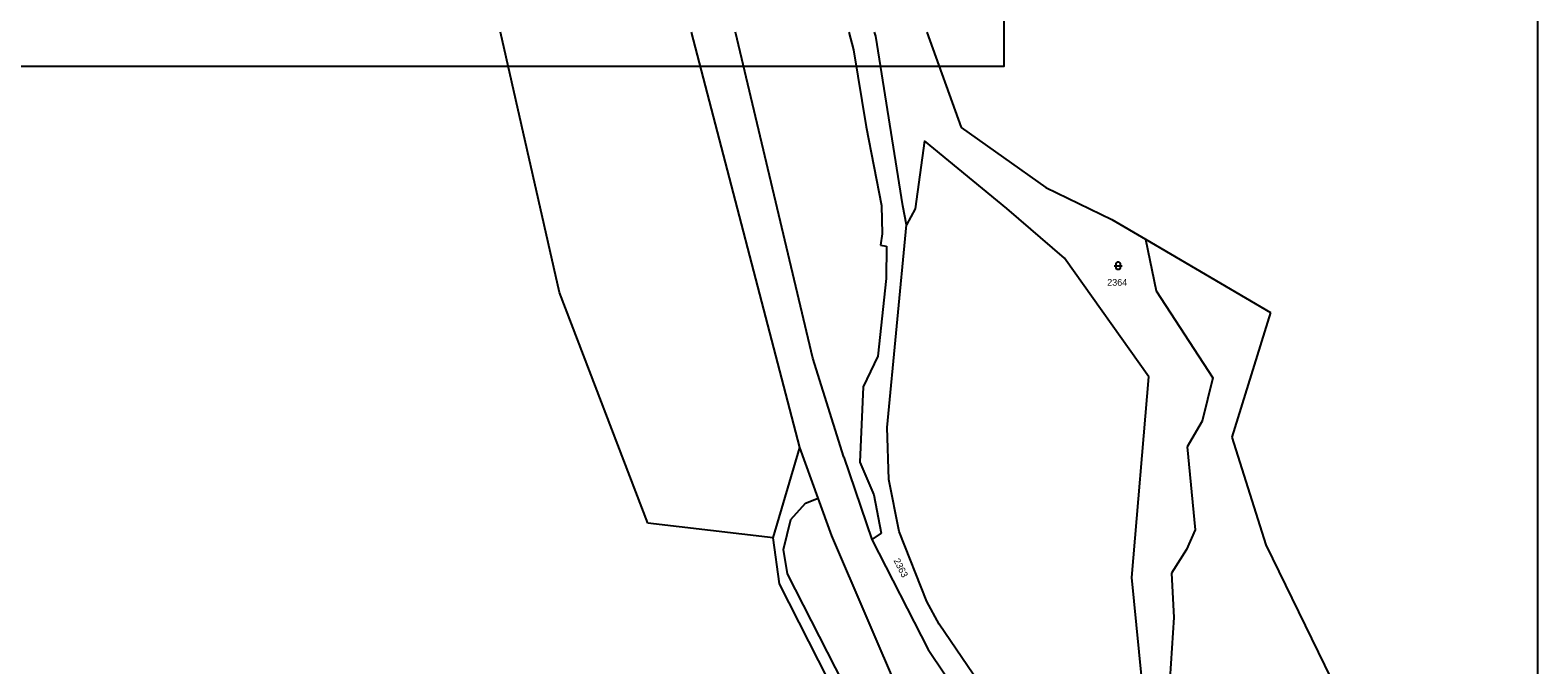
# Model space of a CAD drawing. Extents: x -852001 to -842497, y -1063614 to -1052182.
# Drawn here: x -849131.5 to -848750, y -1053385.6 to -1053225.1 of the extents above; entities that cross this region are included whole.
import ezdxf

# ---------------------------------------------------------------- set-up
doc = ezdxf.new("R2010")
doc.units = 0
for name, color, linetype in [('Default', 7, 'Continuous'), ('KLADY_ZMVM', 7, 'Continuous'), ('KN_HRANICE', 7, 'Continuous'), ('KN_KULTURY', 7, 'Continuous'), ('KN_PARCELY', 7, 'Continuous'), ('LEGENDA', 7, 'Continuous')]:
    doc.layers.add(name, color=color, linetype=linetype)

# ---------------------------------------------------------------- blocks, each defined once
blk = doc.blocks.new('316')
at = {"layer": 'Default'}
for points in [[(-1, 1), (0.27, 1), (1, 1)], [(-0.5, 1.5), (-0.4, 1.79), (-0.15, 1.97), (0.16, 1.97), (0.41, 1.79), (0.51, 1.5), (0.51, 0.5), (0.41, 0.21), (0.16, 0.03), (-0.15, 0.03), (-0.4, 0.21), (-0.5, 0.5), (-0.5, 1.5)]]:
    blk.add_lwpolyline(points, dxfattribs=at)

msp = doc.modelspace()

# ---------------------------------------------------------------- linework, layer by layer
at = {"layer": 'KLADY_ZMVM'}
msp.add_line((-848750, -1053500), (-848750, -1053000), dxfattribs=at)
at = {"layer": 'KN_HRANICE'}
for p, q in [((-848997.5, -1053291.4), (-849012.45, -1053225.59)), ((-848936.74, -1053330.64), (-848964.1, -1053225.59)), ((-848933.4, -1053308.05), (-848952.97, -1053225.59)), ((-848924.31, -1053225.59), (-848923.13, -1053230.03)), ((-848917.5, -1053226.61), (-848917.84, -1053225.59)), ((-848910.7, -1053269.52), (-848917.5, -1053226.61)), ((-848904.61, -1053225.59), (-848895.91, -1053249.67)), ((-848923.13, -1053230.03), (-848919.96, -1053249.53)), ((-848919.96, -1053249.53), (-848916.06, -1053269.39)), ((-848895.91, -1053249.67), (-848874.52, -1053264.9)), ((-848905.2, -1053253.03), (-848907.5, -1053270.25)), ((-848884.39, -1053270.14), (-848905.2, -1053253.03)), ((-848874.52, -1053264.9), (-848857.79, -1053272.92)), ((-848916.06, -1053269.39), (-848915.91, -1053276.62)), ((-848909.7, -1053274.35), (-848910.7, -1053269.52)), ((-848907.5, -1053270.25), (-848909.7, -1053274.35)), ((-848869.78, -1053282.72), (-848884.39, -1053270.14)), ((-848914.62, -1053325.59), (-848909.7, -1053274.35)), ((-848857.79, -1053272.92), (-848849.27, -1053277.91)), ((-848915.91, -1053276.62), (-848916.33, -1053279.44)), ((-848849.27, -1053277.91), (-848846.59, -1053291.04)), ((-848849.27, -1053277.91), (-848817.6, -1053296.47)), ((-848916.33, -1053279.44), (-848914.83, -1053279.68)), ((-848914.83, -1053279.68), (-848914.85, -1053287.87)), ((-848848.43, -1053312.77), (-848869.78, -1053282.72)), ((-848914.85, -1053287.87), (-848916.95, -1053307.56)), ((-848975.18, -1053349.78), (-848997.5, -1053291.4)), ((-848846.59, -1053291.04), (-848832.25, -1053313.05)), ((-848817.6, -1053296.47), (-848827.42, -1053328.03)), ((-848925.57, -1053333.06), (-848933.4, -1053308.05)), ((-848916.95, -1053307.56), (-848920.71, -1053315.28)), ((-848920.71, -1053315.28), (-848921.52, -1053334.36)), ((-848852.74, -1053363.51), (-848848.43, -1053312.77)), ((-848832.25, -1053313.05), (-848834.97, -1053323.98)), ((-848834.97, -1053323.98), (-848838.73, -1053330.45)), ((-848914.18, -1053338.69), (-848914.62, -1053325.59)), ((-848943.5, -1053353.45), (-848936.74, -1053330.64)), ((-848932.07, -1053343.45), (-848936.74, -1053330.64)), ((-848838.73, -1053330.45), (-848836.7, -1053351.46)), ((-848827.42, -1053328.03), (-848818.78, -1053355.27)), ((-848925.57, -1053333.06), (-848918.5, -1053353.87)), ((-848921.52, -1053334.36), (-848917.99, -1053342.58)), ((-848911.62, -1053351.88), (-848914.18, -1053338.69)), ((-848917.99, -1053342.58), (-848916.16, -1053352.31)), ((-848938.98, -1053348.88), (-848935.27, -1053344.69)), ((-848935.27, -1053344.69), (-848932.07, -1053343.45)), ((-848928.59, -1053353), (-848932.07, -1053343.45)), ((-848943.5, -1053353.45), (-848975.18, -1053349.78)), ((-848940.85, -1053356.42), (-848938.98, -1053348.88)), ((-848941.85, -1053365.12), (-848943.5, -1053353.45)), ((-848911.04, -1053394.01), (-848928.59, -1053353)), ((-848916.16, -1053352.31), (-848918.5, -1053353.87)), ((-848918.5, -1053353.87), (-848904.29, -1053381.74)), ((-848904.56, -1053369.55), (-848911.62, -1053351.88)), ((-848836.7, -1053351.46), (-848838.9, -1053356.41)), ((-848939.85, -1053362.61), (-848940.85, -1053356.42)), ((-848838.9, -1053356.41), (-848842.7, -1053362.4)), ((-848818.78, -1053355.27), (-848802.33, -1053389.15)), ((-848924.42, -1053399.45), (-848941.85, -1053365.12)), ((-848921.13, -1053399.1), (-848939.85, -1053362.61)), ((-848849.36, -1053397.56), (-848852.74, -1053363.51)), ((-848842.7, -1053362.4), (-848842.06, -1053373.66)), ((-848901.49, -1053375.29), (-848904.56, -1053369.55)), ((-848842.06, -1053373.66), (-848843.36, -1053392.98)), ((-848869.21, -1053422.76), (-848901.49, -1053375.29)), ((-848904.29, -1053381.74), (-848875.72, -1053424.05))]:
    msp.add_line(p, q, dxfattribs=at)
at = {"layer": 'LEGENDA'}
msp.add_lwpolyline([(-849479.05, -1053234.18), (-848885.05, -1053234.18), (-848885.05, -1052814.18), (-849479.05, -1052814.18)], close=True, dxfattribs=at)

# ---------------------------------------------------------------- block references
at = {"layer": 'KN_KULTURY'}
msp.add_blockref('316', (-848856.17, -1053285.67), dxfattribs=at)

# ---------------------------------------------------------------- texts
at = {"layer": 'KN_PARCELY'}
msp.add_text('2364', height=1.7, dxfattribs=at).set_placement((-848858.95, -1053289.71))
msp.add_text('2363', height=1.7, rotation=297.021, dxfattribs=at).set_placement((-848913.07, -1053359.2))

doc.saveas('drawing.dxf')
